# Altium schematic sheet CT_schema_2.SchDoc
size 276 x 169 mm
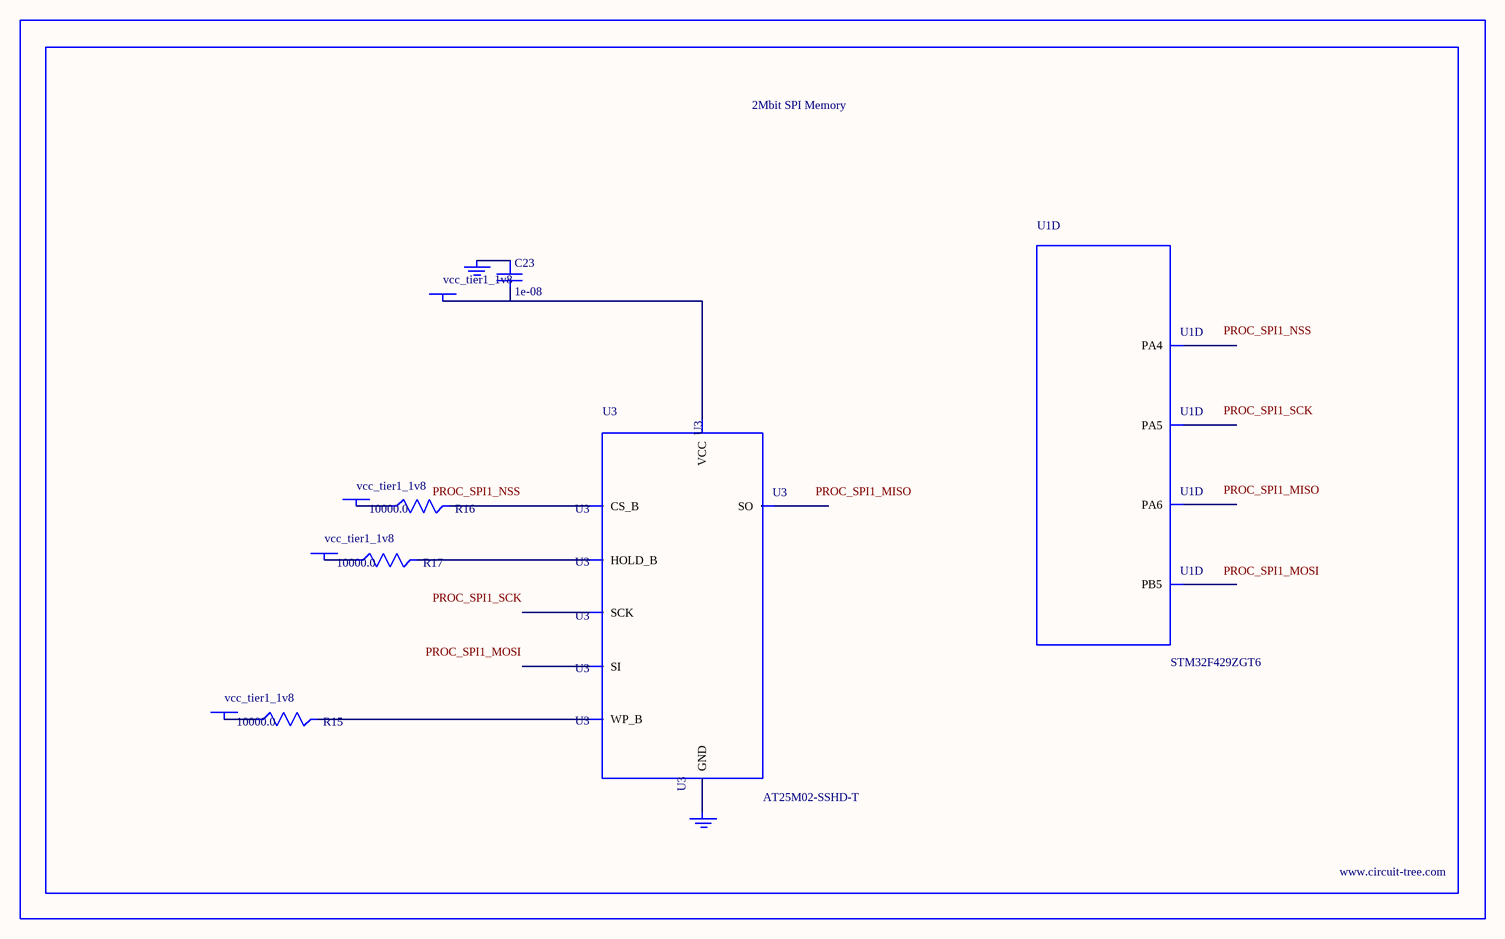
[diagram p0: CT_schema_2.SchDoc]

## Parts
BORDER1  (no value)
C23  1e-08  [C0402]
GND_INSTANCE_1_0  (no value)
GND_INSTANCE_1_1  (no value)
POWER_INSTANCE_1_0  vcc_tier1_1v8
POWER_INSTANCE_1_1  vcc_tier1_1v8
POWER_INSTANCE_1_2  vcc_tier1_1v8
POWER_INSTANCE_1_3  vcc_tier1_1v8
R15  10000.0  [R0603]
R16  10000.0  [R0603]
R17  10000.0  [R0603]
U1  STM32F429ZGT6  [LQFP144]  (part D of 11)
U3  AT25M02-SSHD-T  [SOIC-8]

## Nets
NetC23_1: C23.1 GND_INSTANCE_1_0.0(GND)
NetC23_2: C23.2 POWER_INSTANCE_1_3.0(PWR) U3.8(VCC)
NetGND_INSTANCE_1_1_0: GND_INSTANCE_1_1.0(GND) U3.4(GND)
NetPOWER_INSTANCE_1_0_0: POWER_INSTANCE_1_0.0(PWR) R16.1
NetPOWER_INSTANCE_1_1_0: POWER_INSTANCE_1_1.0(PWR) R15.1
NetPOWER_INSTANCE_1_2_0: POWER_INSTANCE_1_2.0(PWR) R17.1
NetR15_2: R15.2 U3.3(WP_B)
NetR16_2: R16.2 U3.1(CS_B)
NetR17_2: R17.2 U3.7(HOLD_B)

Not connected (* = marked no-connect by the designer): U1 40(PA4) 41(PA5) 42(PA6) 135(PB5); U3 2(SO) 5(SI) 6(SCK)

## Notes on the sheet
- Labels drawn without touching a wire or pin: PROC_SPI1_MISO, PROC_SPI1_MOSI, PROC_SPI1_NSS, PROC_SPI1_SCK

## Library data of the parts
BORDER1 = BORDER_PAGE1
C23 = C0402C103K3RAC
GND_INSTANCE_1_0 GND_INSTANCE_1_1 = GND
POWER_INSTANCE_1_0-POWER_INSTANCE_1_3 = PWR
R15-R17 = RC0603JR-0710KL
